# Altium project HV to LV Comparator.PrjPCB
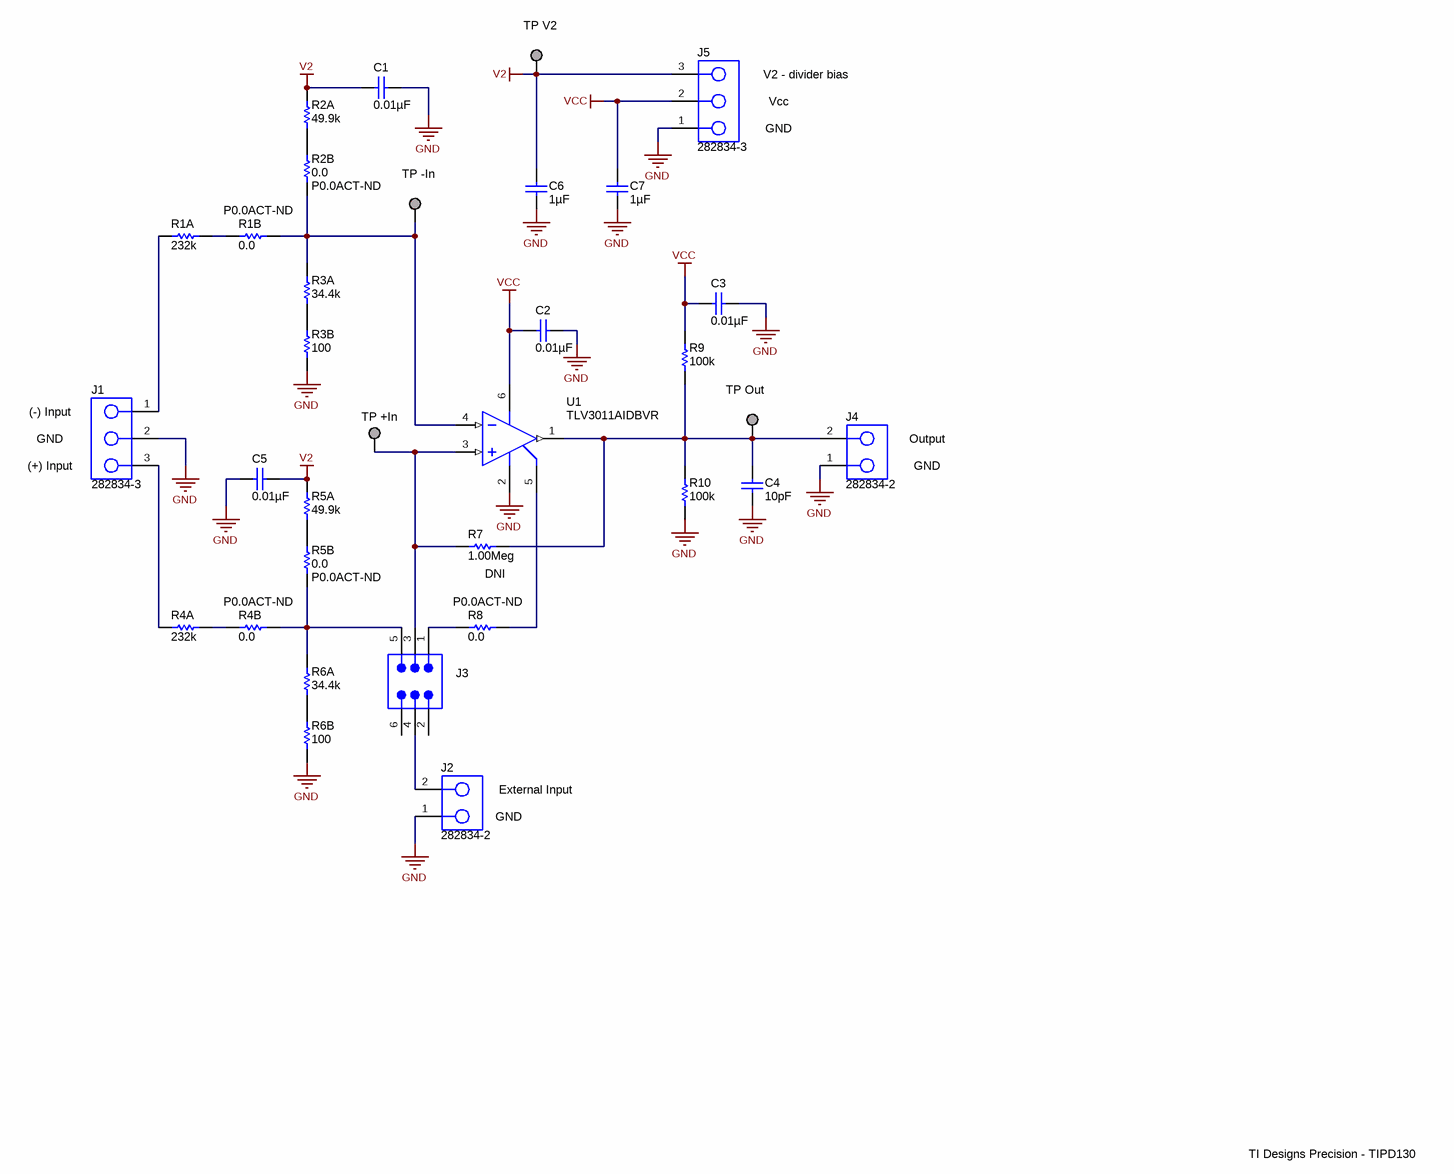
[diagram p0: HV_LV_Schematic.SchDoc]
TechSupport: http://e2e.ti.com; SCH_Rev: 0; PRJ_Title: TI Designs Precision; PRJ_Customer: Precision Linear; CopyrightYear: 2014
2 sheets, 43 parts. Net scope: global (net labels, ports and power ports of the same name join across sheets).
Board file: HV to LV Comparator.PcbDoc
Sheets:
  HV_LV_Schematic.SchDoc
  Hardware_ANSI-B.SchDoc

## Sheet HV_LV_Schematic.SchDoc: Schematic for LitTIDU039
size 431 x 279 mm; Date: Not shown in title block; ApprovedBy: Not shown in title block; CheckedBy: Not shown in title block; Author: Not shown in title block; CompanyName: Not shown in title block; Engineer: Not shown in title block; Organization: Not shown in title block; Address1: Not shown in title block; Address2: Not shown in title block; Address3: Not shown in title block; Address4: Not shown in title block; DocumentNumber: 1; Revision: Use project parameter SCH_Rev; SheetNumber: 1; SheetTotal: 1; PageSetup: Record=PageOptions|CenterHorizontal=True|CenterVertical=True|PrintScale=0.96|XCorrection=1.00|YCorrection=1.00|PrintKind=0|BorderSize=5000000|LeftOffset=0|BottomOffset=0|Orientation=2|PaperLength=1000|PaperWidth=1000|Scale=100|PaperSource=15|PrintQuality=600|MediaType=1|DitherType=10|PaperKind=11x17|PrintScaleMode=1

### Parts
C1  ValueDisplayed: 0.01µF  [0805_HV]  (hidden comment: C2012X7R2A103K)
C2  ValueDisplayed: 0.01µF  [0805_HV]  (hidden comment: C2012X7R2A103K)
C3  ValueDisplayed: 0.01µF  [0805_HV]  (hidden comment: C2012X7R2A103K)
C4  ValueDisplayed: 10pF  [0805_HV]  (hidden comment: C0805C100J1GACTU)
C5  ValueDisplayed: 0.01µF  [0805_HV]  (hidden comment: C2012X7R2A103K)
C6  ValueDisplayed: 1µF  [1206]  (hidden comment: 12063C105KAT2A)
C7  ValueDisplayed: 1µF  [1206]  (hidden comment: 12063C105KAT2A)
J1  282834-3  [3 Contact Terminal Block]
J2  282834-2  [2 Contact Terminal Block]
J3  TSW-103-07-G-D  [TSW-103-07-G-D]  (value not drawn)
J4  282834-2  [2 Contact Terminal Block]
J5  282834-3  [3 Contact Terminal Block]
R1A  value 232k  [0805_HV]  (hidden comment: RT0805BRD07232KL)
R1B  value 0.0  Supplier Part Number 1: P0.0ACT-ND  [0805]  (hidden comment: Used in BOM report)
R2A  value 49.9k  [0805_HV]  (hidden comment: RT0805BRD0749K9L)
R2B  value 0.0  Supplier Part Number 1: P0.0ACT-ND  [0805]  (hidden comment: Used in BOM report)
R3A  value 34.4k  [0805_HV]  (hidden comment: RT0805BRD0734K4L)
R3B  value 100  [0805_HV]  (hidden comment: RT0805BRD07100RL)
R4A  value 232k  [0805_HV]  (hidden comment: RT0805BRD07232KL)
R4B  value 0.0  Supplier Part Number 1: P0.0ACT-ND  [0805]  (hidden comment: Used in BOM report)
R5A  value 49.9k  [0805_HV]  (hidden comment: RT0805BRD0749K9L)
R5B  value 0.0  Supplier Part Number 1: P0.0ACT-ND  [0805]  (hidden comment: Used in BOM report)
R6A  value 34.4k  [0805_HV]  (hidden comment: RT0805BRD0734K4L)
R6B  value 100  [0805_HV]  (hidden comment: RT0805BRD07100RL)
R7  value 1.00Meg  [0805_HV]  (hidden comment: CRCW08051M00FKEA)  (no BOM)
R8  value 0.0  Supplier Part Number 1: P0.0ACT-ND  [0805]  (hidden comment: Used in BOM report)
R9  value 100k  [0805_HV]  (hidden comment: CRCW0805100KJNEA)
R10  value 100k  [0805_HV]  (hidden comment: CRCW0805100KJNEA)
TP_+In  TESTPOINT  [TESTPOINT]  (value not drawn)  (no BOM)
TP_-In  TESTPOINT  [TESTPOINT]  (value not drawn)  (no BOM)
TP_Out  TESTPOINT  [TESTPOINT]  (value not drawn)  (no BOM)
TP_V2  TESTPOINT  [TESTPOINT]  (value not drawn)  (no BOM)
U1  TLV3011AIDBVR  [DBV0006A_M]

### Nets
GND: C1.1 C2.1 C3.1 C4.2 C5.2 C6.2 C7.2 J1.2 J2.1 J4.1 J5.1 R3B.1 R6B.1 R10.1 U1.2(V-)
V2: C1.2 C5.1 C6.1 J5.3 R2A.2 R5A.2 TP_V2.1
VCC: C2.2 C3.2 C7.1 J5.2 R9.2 U1.6(V+)
NetC4_1: C4.1 J4.2 R7.2 R9.1 R10.2 TP_Out.1 U1.1(OUT)
NetJ1_1: J1.1 R1A.1
NetJ1_3: J1.3 R4A.1
NetJ2_2: J2.2 J3.4
NetJ3_1: J3.1 R8.1
NetJ3_3: J3.3 R7.1 TP_+In.1 U1.3(IN+)
NetJ3_5: J3.5 R4B.2 R5B.1 R6A.2
NetR1A_2: R1A.2 R1B.1
NetR1B_2: R1B.2 R2B.1 R3A.2 TP_-In.1 U1.4(IN-)
NetR2A_1: R2A.1 R2B.2
NetR3A_1: R3A.1 R3B.2
NetR4A_2: R4A.2 R4B.1
NetR5A_1: R5A.1 R5B.2
NetR6A_1: R6A.1 R6B.2
NetR8_2: R8.2 U1.5(REF)

Not connected (* = marked no-connect by the designer): J3 2 6

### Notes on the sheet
- Vcc
- V2 - divider bias
- GND
- (near J1) (-) Input
- Output
- (near J1) (+) Input
- (near R7) DNI
- (near J2) External Input
- TI Designs Precision - TIPD130

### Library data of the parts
C1-C3 C5 = C2012X7R2A103K: CAP, CERM, 0.01uF, 100V, +/-10%, X7R, 0805; Manufacturer: TDK; Polarized: N; CompType: Capacitor; U/M: EA; Cap_F: 0.00000001; Tolerance_%: 10; ESR_Ohm: 0.0571; Value1: 0.0571 ohm; VDC_V: 100; TaMin_C: -55; TaMax_C: 125; Cap_Case: 0805
C4 = C0805C100J1GACTU: CAP, CERM, 10pF, 100V, +/-5%, C0G/NP0, 0805; Manufacturer: Kemet; Polarized: N; CompType: Capacitor; U/M: EA; Cap_F: 0.00000000001; Tolerance_%: 5; ESR_Ohm: 0.285; Value1: 0.285 ohm; VDC_V: 100; IRMS_A: 0.221; TaMin_C: -55; TaMax_C: 125; Cap_Case: 0805
C6 C7 = 12063C105KAT2A: CAP, CERM, 1uF, 25V, +/-10%, X7R, 1206; Manufacturer: AVX; Polarized: N; CompType: Capacitor; U/M: EA; Cap_F: 0.000001; Tolerance_%: 10; ESR_Ohm: 0.013; Value1: 0.013 ohm; VDC_V: 25; TaMin_C: -55; TaMax_C: 125
J1 J5 = TERM BLOCK 3POS SIDE ENT: 3 contact eurostyle terminal block; Manufacturer: TE Connectivity; SymbolVersion: use current date i.e. 2008-05-20; SymbolCreator: Use a-id; CompType: Used in some BOM reports.  Useful for finding later.; U/M: EA, IN, or GM
J2 J4 = TERM BLOCK 2POS SIDE ENT: 2 contact eurostyle terminal block; Manufacturer: TE Connectivity; SymbolVersion: use current date i.e. 2008-05-20; SymbolCreator: Use a-id; CompType: Used in some BOM reports.  Useful for finding later.; U/M: EA, IN, or GM
J3 = TSW-103-07-G-D: Header, TH, 100mil, 3x2, Gold plated, 230 mil above insulator; Manufacturer: Samtec; U/M: EA
R1A R4A = RT0805BRD07232KL: RES, 232k ohm, 0.1%, 0.125W, 0805; Manufacturer: Yageo America; CompType: Resistor; Res_ohm: 232000; Tolerance_%: 0.1; Power_W: 0.125; VDC_V: 150; TempCo: 25 ppm/C; EIA_Code: E192; U/M: EA
R1B R2B R4B R5B R8 = Resistor: RES 0.0 OHM 1/8W JUMP 0805 SMD; U/M: EA; Tolerance_%: Jumper; Power_W: 0.125W, 1/8W
R2A R5A = RT0805BRD0749K9L: RES, 49.9k ohm, 0.1%, 0.125W, 0805; Manufacturer: Yageo America; CompType: Resistor; Res_ohm: 49900; Value_Code: 49k9; Tolerance_%: 0.1; Power_W: 0.125; VDC_V: 150; TempCo: 25 ppm/C; EIA_Code: E192; U/M: EA
R3A R6A = RT0805BRD0734K4L: RES, 34.4k ohm, 0.1%, 0.125W, 0805; Manufacturer: Yageo America; CompType: Resistor; Res_ohm: 34400; Value_Code: 34k4; Tolerance_%: 0.1; Power_W: 0.125; VDC_V: 150; TempCo: 25 ppm/C; EIA_Code: E192; U/M: EA
R3B R6B = RT0805BRD07100RL: RES, 100 ohm, 0.1%, 0.125W, 0805; Manufacturer: Yageo America; CompType: Resistor; Value_Code: 100R; Tolerance_%: 0.1; Power_W: 0.125; VDC_V: 150; TempCo: 25 ppm/C; EIA_Code: E192; U/M: EA
R7 = CRCW08051M00FKEA: RES, 1.00Meg ohm, 1%, 0.125W, 0805; Manufacturer: Vishay-Dale; CompType: Resistor; Res_ohm: 1000000; Value_Code: 1M00; Tolerance_%: 1; Power_W: 0.125; VDC_V: 150; TempCo: 100 ppm/C; EIA_Code: E96; U/M: EA
R9 R10 = CRCW0805100KJNEA: RES, 100k ohm, 5%, 0.125W, 0805; Manufacturer: Vishay-Dale; CompType: Resistor; Res_ohm: 100000; Tolerance_%: 5; Power_W: 0.125; VDC_V: 150; TempCo: 200 ppm/C; EIA_Code: E24; U/M: EA
TP_+In TP_-In TP_Out TP_V2 = TESTPOINT: TEST POINT.  No entry in BOM.
U1 = TLV3011AIDBVR: Nanopower, 1.8V, SOT23 Comparator with Voltage Reference; Manufacturer: Texas Instruments; SymbolVersion: use current date i.e. 2008-05-20; SymbolCreator: Use a-id; CompType: Used in some BOM reports.  Useful for finding later.; U/M: EA, IN, or GM

## Sheet Hardware_ANSI-B.SchDoc
size 431 x 279 mm; Date: Not shown in title block; ApprovedBy: Not shown in title block; CheckedBy: Not shown in title block; Author: Not shown in title block; CompanyName: Not shown in title block; Engineer: Not shown in title block; Organization: Not shown in title block; Address1: Not shown in title block; Address2: Not shown in title block; Address3: Not shown in title block; Address4: Not shown in title block; DocumentNumber: 1; Revision: Use project parameter SCH_Rev; SheetNumber: 1; SheetTotal: 1; PageSetup: Record=PageOptions|CenterHorizontal=True|CenterVertical=True|PrintScale=1.00|XCorrection=1.00|YCorrection=1.00|PrintKind=0|BorderSize=5000000|LeftOffset=0|BottomOffset=0|Orientation=2|PaperLength=1000|PaperWidth=1000|Scale=100|PaperSource=15|PrintQuality=600|MediaType=1|DitherType=10|PaperKind=Letter|PrintScaleMode=1
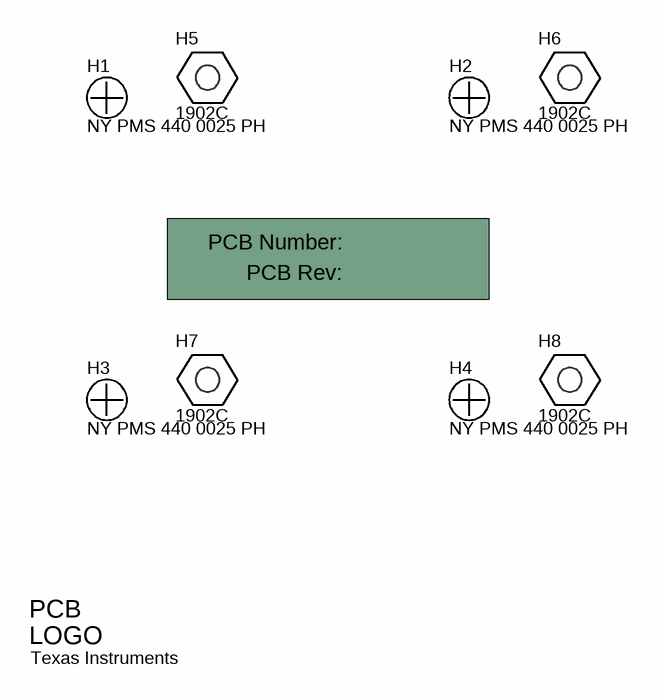
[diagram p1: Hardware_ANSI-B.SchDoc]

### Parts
!PCB  Printed Circuit Board  (value not drawn)  (mechanical)
H1  NY PMS 440 0025 PH  [NY PMS 440 0025 PH]
H2  NY PMS 440 0025 PH  [NY PMS 440 0025 PH]
H3  NY PMS 440 0025 PH  [NY PMS 440 0025 PH]
H4  NY PMS 440 0025 PH  [NY PMS 440 0025 PH]
H5  1902C  [Keystone_1902C]
H6  1902C  [Keystone_1902C]
H7  1902C  [Keystone_1902C]
H8  1902C  [Keystone_1902C]
Logo1  Texas Instruments  [TI_Stacked_Overlay_Small]  (no BOM)

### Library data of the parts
!PCB = PCB: Manufacturer: Any; SymbolCreator: a0412235
H1-H4 = NY PMS 440 0025 PH: Machine Screw, Round, #4-40 x 1/4, Nylon, Philips panhead; Manufacturer: B&F Fastener Supply; CompType: Hardware; SymbolCreator: codlsc; U/M: EA
H5-H8 = 1902C: Standoff, Hex, 0.5"L #4-40 Nylon; Manufacturer: Keystone; CompType: Hardware
Logo1 = TI_Logo: Texas Instrument Corporate Signature; SymbolCreator: codlsc

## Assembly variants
001: all parts fitted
